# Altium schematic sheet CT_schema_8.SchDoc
size 274 x 160 mm
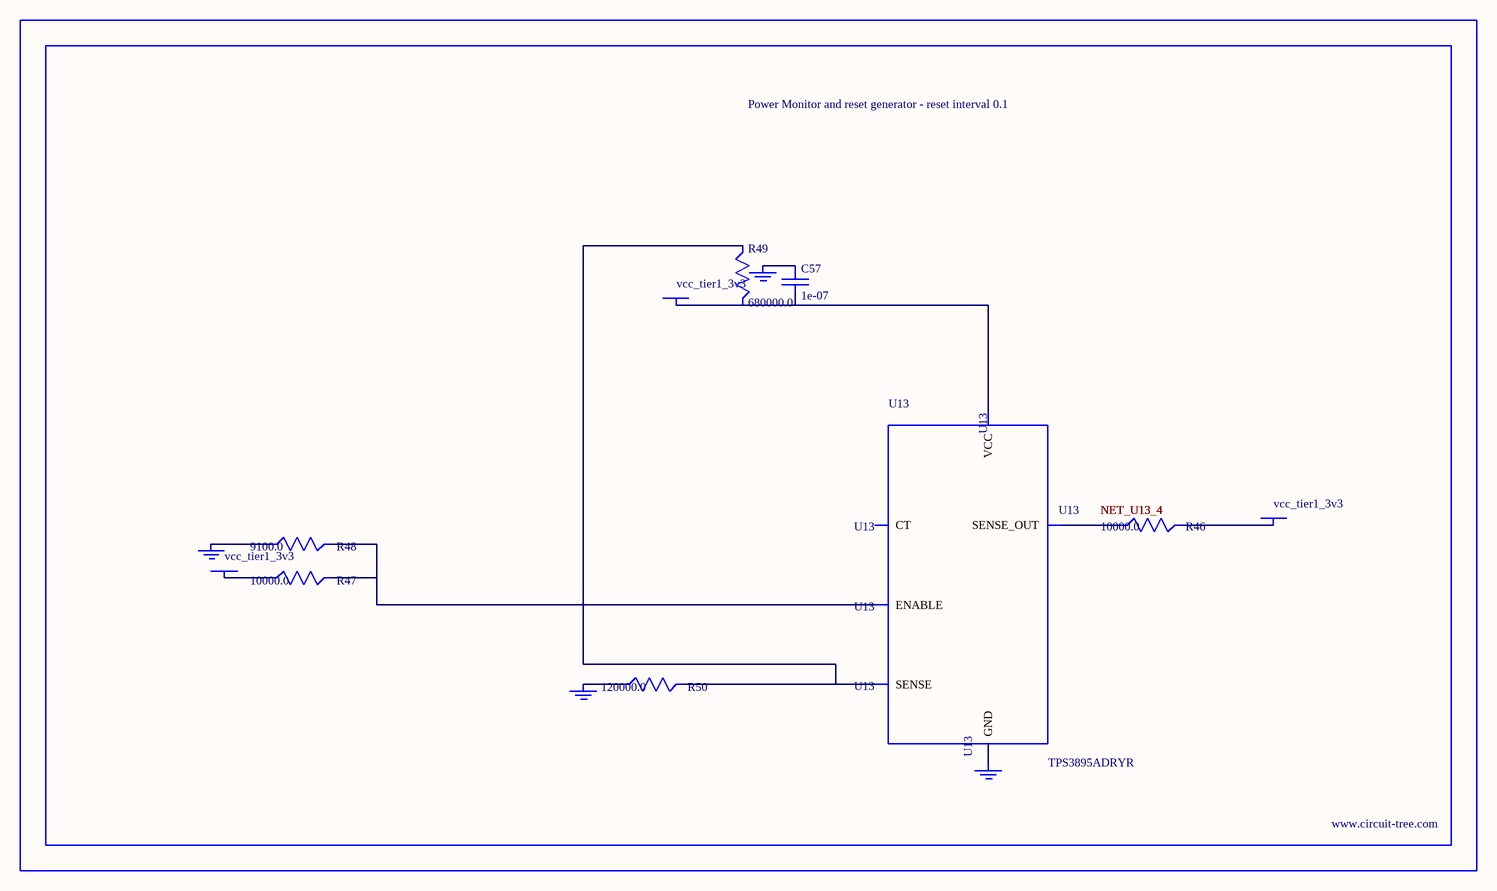
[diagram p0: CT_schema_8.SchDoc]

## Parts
BORDER7  (no value)
C57  1e-07  [C0402]
GND_INSTANCE_7_0  (no value)
GND_INSTANCE_7_1  (no value)
GND_INSTANCE_7_2  (no value)
GND_INSTANCE_7_3  (no value)
POWER_INSTANCE_7_0  vcc_tier1_3v3
POWER_INSTANCE_7_1  vcc_tier1_3v3
POWER_INSTANCE_7_2  vcc_tier1_3v3
R46  10000.0  [R0603]
R47  10000.0  [R0603]
R48  9100.0  [R0603]
R49  680000.0  [R0603]
R50  120000.0  [R0603]
U13  TPS3895ADRYR  [SON-6]

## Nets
NetC57_1: C57.1 GND_INSTANCE_7_2.0(GND)
NetC57_2: C57.2 POWER_INSTANCE_7_2.0(PWR) R49.2 U13.6(VCC)
NetGND_INSTANCE_7_0_0: GND_INSTANCE_7_0.0(GND) R48.1
NetGND_INSTANCE_7_1_0: GND_INSTANCE_7_1.0(GND) R50.1
NetGND_INSTANCE_7_3_0: GND_INSTANCE_7_3.0(GND) U13.2(GND)
NetPOWER_INSTANCE_7_0_0: POWER_INSTANCE_7_0.0(PWR) R47.1
NetPOWER_INSTANCE_7_1_0: POWER_INSTANCE_7_1.0(PWR) R46.2
NetR46_1: R46.1 U13.4(SENSE_OUT)
NetR47_2: R47.2 R48.2 U13.1(ENABLE)
NetR49_1: R49.1 R50.2 U13.3(SENSE)

Not connected (* = marked no-connect by the designer): U13 5(CT)

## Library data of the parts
BORDER7 = BORDER_PAGE7
C57 = C0402C104K3RACTU
GND_INSTANCE_7_0-GND_INSTANCE_7_3 = GND
POWER_INSTANCE_7_0-POWER_INSTANCE_7_2 = PWR
R46 R47 = RC0603JR-0710KL
R48 = RC0603JR-079K1L
R49 = RC0603JR-07680KL
R50 = RC0603JR-07120KL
